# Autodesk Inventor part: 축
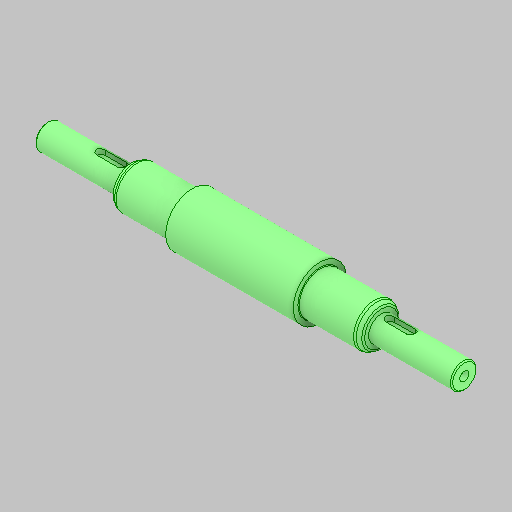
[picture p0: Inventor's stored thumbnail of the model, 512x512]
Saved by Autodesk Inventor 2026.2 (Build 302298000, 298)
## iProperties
Created: 2026-06
Part Number: 축
Material: 강철, 탄소
Document SubType Name: Modeling
Designer: sec7
Density: 7.85 g/cm^3
Appearance: 기본값
Author: jhkim
Sending System: Autodesk Inventor 2027
Preprocessor: ST-DEVELOPER v20.1
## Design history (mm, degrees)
feature "솔리드1"
node "솔리드2"
